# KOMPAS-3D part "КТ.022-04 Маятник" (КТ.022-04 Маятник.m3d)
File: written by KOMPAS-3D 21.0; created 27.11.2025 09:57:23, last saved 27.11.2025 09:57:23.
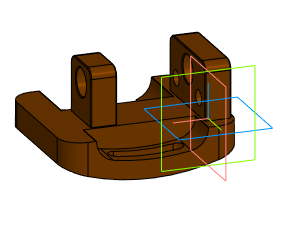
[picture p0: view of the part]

Document properties: Автор: Марсель; Организация: Марсель; Полное имя файла: C:\Users\User\Desktop\Pelorus PRO доработки\Маятник\КТ.022-04 Маятник.m3d

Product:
- Part/product: КТ.022-04 Маятник
    Комментарий: Марсель

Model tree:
1. Операция без истории:1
